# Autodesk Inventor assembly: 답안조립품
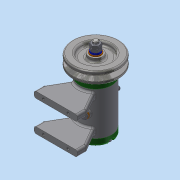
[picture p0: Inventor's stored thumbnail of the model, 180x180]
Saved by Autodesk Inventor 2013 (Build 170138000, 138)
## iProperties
Created: 2018-05
Part Number: 답안조립품
Document SubType Name: Assembly
Designer: dgall
Author: dgall
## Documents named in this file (16)
- C:\Users\dgall\Desktop\480507V1014\답안조립품.iam
- C:\Users\dgall\Desktop\480507V1014\본체.ipt
- C:\Users\dgall\Desktop\480507V1014\뒤커버.ipt
- C:\Users\dgall\Desktop\480507V1014\앞커버.ipt
- C:\Users\dgall\Desktop\480507V1014\베어링 6002.ipt
- C:\Users\dgall\Desktop\480507V1014\축.ipt
- C:\Users\dgall\Desktop\480507V1014\오일 실 15 25 7.ipt
- C:\Users\dgall\Desktop\480507V1014\키 3x3x12.ipt
- C:\Users\dgall\Desktop\480507V1014\V벨트풀리.ipt
- C:\Users\dgall\Desktop\480507V1014\와셔 8x17.ipt
- C:\Users\dgall\Desktop\480507V1014\너트 M8.ipt
- C:\Users\dgall\Desktop\480507V1014\스프링와셔 8.ipt
- C:\Users\dgall\Desktop\480507V1014\볼트 M6x8.ipt
- C:\Users\dgall\Desktop\480507V1014\와셔 6x11.5.ipt
- C:\Users\dgall\Desktop\480507V1014\니플 M6x0.75.ipt
- C:\Users\dgall\Desktop\480507V1014\볼트 M4x12.ipt
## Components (1 placed, 1 different names)
1. V벨트풀리:1
